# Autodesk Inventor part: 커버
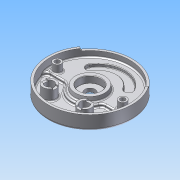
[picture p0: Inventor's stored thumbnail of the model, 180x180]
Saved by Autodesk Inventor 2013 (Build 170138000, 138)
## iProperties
Company: 한국ATC센터
Created: 2015-04
Part Number: 커버
Document SubType Name: Modeling
Designer: KYOUNG IL JANG
Density: 2.71 g/cm^3
Material: 알루미늄-6061
Mass: 1067.78 g
Surface Area: 1019.64 cm^2
Volume: 394.015 cm^3
Author: KYOUNG IL JANG
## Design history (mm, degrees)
sketch "스케치1"
  geometry: L1 (-59, -19)-(-59, 19); L2 (59, 19)-(59, -19); L3 (-41, 19)-(-41, -19); L4 (41, -19)-(41, 19); L5 (38.527, 33.023)-(55.442, 39.179); L6 (-38.527, 33.023)-(-55.442, 39.179); C1 r 90 at (0, 0); C2 r 95 at (0, 0); A1 r 59 centre (0, 19) between (59, 19) and (-59, 19); A2 r 59 centre (0, -19) between (-59, -19) and (59, -19); A3 r 41 centre (0, -19) between (-41, -19) and (41, -19); A4 r 41 centre (0, 19) between (41, 19) and (-41, 19); 2 further points
  constraints: 12 end point, 12 point on circle, 6 centre point, 4 tangent, 2 parallel, 2 point on line, 1 coincident, 1 horizontal alignment, 1 midpoint, 1 vertical, 1 vertical alignment, 3 other
  dimensions: "d2" = 180 diameter of C1; "d3" = 156 dimension on A2 A1; "d4" = 118 distance between parallel lines of L2 L1; "d5" = 18 distance between parallel lines of L2 L4; "d8" = 190 diameter of C2; "d120" = 140 deg angle of L6 L5; "d121" = 110 deg dimension on A1.centre point (0, 0) L5.end
extrude "돌출1" new body sketch "스케치1" distance "d6" = 14; taper "d7" = 0 deg
extrude "돌출2" join sketch "스케치1" distance "d9" = 13; taper "d10" = 0 deg
extrude "돌출3" cut sketch "스케치1" distance "d11" = 7; taper "d12" = 0 deg
sketch "스케치2"
  geometry: C1 r 11.5 at (0, 0); 1 further point
  constraints: 1 centre point, 1 coincident
  dimensions: "d13" = 23 diameter of C1
extrude "돌출4" cut sketch "스케치2" stored distance "d14" = 7; taper "d15" = 0 deg
fillet "모깎기1"
fillet "모깎기2"
sketch "스케치3"
  geometry: L1 (-73.724, 51.622)-(-77.819, 54.49); L2 (73.724, 51.622)-(77.819, 54.49); L3 (0, 0)-(0, -90); A1 r 95 centre (0, 0) between (-77.819, 54.49) and (77.819, 54.49) reference; A2 r 90 centre (0, 0) between (-73.724, 51.622) and (73.724, 51.622) reference; 1 further point
  constraints: 6 end point, 5 point on circle, 1 point on line, 1 vertical, 1 other
  dimensions: "d16" = 250 deg dimension on L2 L1
extrude "돌출5" join sketch "스케치3" distance "d17" = 5; taper "d18" = 0 deg
hole "구멍1" diameter "d21" = 50; stored, may be unused: countersink angle "d25" = 90 deg, drill point angle "d27" = 0 deg; dims "d19" = 10, "d20" = 10, "d22" = 6, "d23" = 4, "d24" = 2, "d26" = 5
fillet "모깎기3" dims "d28" = 0.3
fillet "모깎기5" dims "d30" = 3
sketch "스케치4"
  geometry: C1 r 35 at (0, 0); C2 r 25 at (0, 0); 1 further point
  constraints: 2 centre point, 1 coincident
  dimensions: "d32" = 70 diameter of C1 (derived); "d36" = 10 radial gap between concentric circles of C1 C2
extrude "돌출6" join sketch "스케치4" distance "d33" = 10; taper "d34" = 0 deg
feature "면 기울기2" dims angle "d37" = 10 deg
chamfer "모따기1" distance "d39" = 1; stored, may be unused: second distance "d40" = 2, angle "d41" = 45 deg
fillet "모깎기7" dims "d42" = 5
sketch "스케치5"
  geometry: L1 (-40.249, -12)-(-89.196, -12); L2 (40.249, -12)-(89.196, -12); A1 r 90 centre (0, 0) between (-89.196, -12) and (89.196, -12) reference; A2 r 42 centre (0, 0) between (-40.249, -12) and (40.249, -12); 1 further point
  constraints: 4 end point, 4 point on circle, 1 centre point, 1 collinear, 1 horizontal, 1 point on line
  dimensions: "d43" = 48 radial gap between concentric circles of A1 A2; "d44" = 12 distance from line of point (0, 0) L1
extrude "돌출7" cut sketch "스케치5" stored distance "d45" = 10; taper "d46" = 0 deg
fillet "모깎기8" dims "d47" = 10
chamfer "모따기2" distance "d49" = 1; stored, may be unused: second distance "d50" = 2, angle "d51" = 45 deg
sketch "스케치7"
  geometry: L1 (36.062, 36.062)-(50.912, 50.912); L2 (-36.062, 36.062)-(-50.912, 50.912); A1 r 72 centre (0, 0) between (50.912, 50.912) and (-50.912, 50.912); A2 r 51 centre (0, 0) between (36.062, 36.062) and (-36.062, 36.062); 1 further point
  constraints: 8 point on circle, 4 end point, 2 centre point, 2 point on line, 1 coincident, 1 horizontal alignment
  dimensions: "d54" = 72 radius of A1; "d55" = 21 radial gap between concentric circles of A1 A2; "d56" = 90 deg angle of L2 L1
extrude "돌출8" join sketch "스케치7" distance "d57" = 5; taper "d58" = 0 deg
fillet "모깎기10" dims "d59" = 5
fillet "모깎기11" dims "d60" = 5
fillet "모깎기12" dims "d61" = 3
sketch "스케치6"
  geometry: C1 r 68 at (0, 0); 1 further point
  constraints: 1 centre point, 1 other
  dimensions: "d119" = 136 diameter of C1
feature "엠보싱1" sketch "스케치6" dims "d62" = 0.5, "d63" = 0
sketch "스케치8"
  geometry: C1 r 9 at (74, 0); C2 r 9 at (-74, 0); A1 r 74 centre (0, 0) between (74, 0) and (-74, 0); 1 further point
  constraints: 3 centre point, 2 horizontal alignment, 2 point on circle, 1 coincident, 1 equal radius
  dimensions: "d64" = 18 diameter of C1; "d65" = 148 diameter of A1
extrude "돌출9" join sketch "스케치8" stored distance "d66" = 5; taper "d67" = 0 deg
sketch "스케치11"
  geometry: C1 r 15 at (40, -52); C2 r 15 at (-40, -52); 1 further point
  constraints: 2 centre point, 1 equal radius, 1 horizontal alignment
  dimensions: "d83" = 52 vertical distance of point (0, 0) C1.centre; "d84" = 80 distance of C2.centre C1.centre; "d85" = 40 horizontal distance of point (0, 0) C1.centre (= 0.5 x d84); "d86" = 30 diameter of C1
extrude "돌출10" join sketch "스케치11" stored distance "d87" = 5; taper "d88" = 0 deg
node "구멍3"
node "구멍5"
hole "구멍6" diameter "d93" = 20; stored, may be unused: countersink angle "d97" = 90 deg, drill point angle "d99" = 118 deg; dims "d91" = 10, "d92" = 10, "d94" = 6, "d95" = 4, "d96" = 2, "d98" = 8
hole "구멍7" diameter "d102" = 20; stored, may be unused: countersink angle "d106" = 90 deg, drill point angle "d108" = 118 deg; dims "d100" = 10, "d101" = 10, "d103" = 6, "d104" = 4, "d105" = 2, "d107" = 8
sketch "스케치13"
  geometry: L1 (6, -13.748)-(6, -8); L2 (6, 8)-(6, 13.748); L3 (-6, -13.748)-(-6, -8); L4 (-6, 8)-(-6, 13.748); L5 (-66.252, -6)-(-72, -6); L6 (-88, -6)-(-93.748, -6); L7 (-66.252, 6)-(-72, 6); L8 (-88, 6)-(-93.748, 6); A1 r 15 centre (0, 0) between (6, -13.748) and (6, 13.748) reference; A2 r 10 centre (0, 0) between (6, -8) and (6, 8) reference; A3 r 15 centre (-80, 0) between (-66.252, -6) and (-93.748, -6) reference; A4 r 10 centre (-80, 0) between (-72, -6) and (-88, -6) reference; 1 further point
  constraints: 16 end point, 16 point on circle, 4 equal length, 3 collinear, 2 point on line, 1 perpendicular, 1 vertical
  dimensions: "d109" = 12 distance between parallel lines of L3 L1; "d110" = 6 distance from line of A1.centre L1 (= 0.5 x d109); "d111" = 12 distance between parallel lines of L7 L5; "d112" = 6 distance from line of A3.centre L5 (= 0.5 x d111)
extrude "돌출12" cut sketch "스케치13" distance "d113" = 3; taper "d114" = 0 deg
fillet "모깎기13" dims "d115" = 3
fillet "모깎기14" dims "d116" = 1
node "솔리드1"
sketch "스케치9"
  geometry: 1 further point
hole "구멍2" sketch "스케치9" diameter "d68" = 11; stored, may be unused: countersink angle "d72" = 90 deg, drill point angle "d74" = 0 deg; dims "d69" = 6, "d70" = 18, "d71" = 11, "d73" = 8
sketch "스케치10"
  geometry: 1 further point
hole "구멍4" sketch "스케치10" diameter "d75" = 11; stored, may be unused: countersink angle "d79" = 90 deg, drill point angle "d81" = 0 deg; dims "d76" = 6, "d77" = 18, "d78" = 11, "d80" = 8
